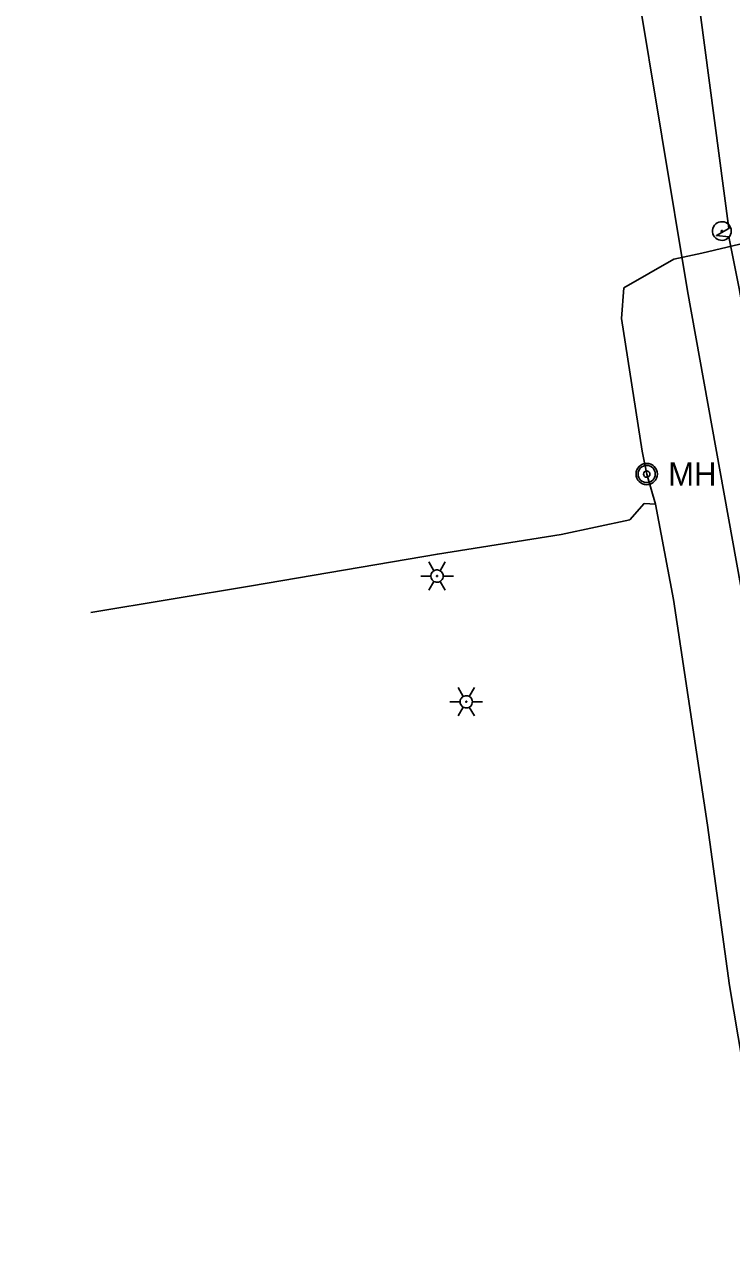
# Model space of a CAD drawing. Extents: x 596028 to 606371, y 330010 to 403088.
# Drawn here: x 604536.2 to 604700.8, y 336030.9 to 336317.8 of the extents above; entities that cross this region are included whole.
import ezdxf

# ---------------------------------------------------------------- set-up
doc = ezdxf.new("R2010")
doc.units = 0
for name, color, linetype in [('Default', 7, 'Continuous'), ('E_LTG', 7, 'Continuous'), ('E_LTG_CID', 7, 'Continuous'), ('E_UTL_E', 7, 'Continuous'), ('E_UTL_E_UG', 7, 'Continuous'), ('E_UTL_FO_UG_QWEST', 7, 'Continuous')]:
    doc.layers.add(name, color=color, linetype=linetype)

# ---------------------------------------------------------------- blocks, each defined once
blk = doc.blocks.new('MH')
at = {"layer": 'Default'}
for radius in [15.2, 12.2, 4.57]:
    blk.add_circle((0, 0), radius, dxfattribs=at)
blk.add_text('MH', height=32.92, dxfattribs=at).set_placement((30.5, -16.5))

msp = doc.modelspace()

# ---------------------------------------------------------------- linework, layer by layer
at = {"layer": 'E_LTG'}
for points in [[(604700.74, 336269.8), (604700.7, 336270.21), (604700.58, 336270.61), (604700.39, 336270.97), (604700.14, 336271.3), (604699.83, 336271.57), (604699.47, 336271.78), (604699.08, 336271.91), (604698.67, 336271.97), (604698.25, 336271.95), (604697.85, 336271.85), (604697.48, 336271.68), (604697.14, 336271.44), (604696.85, 336271.14), (604696.63, 336270.79), (604696.48, 336270.41), (604696.4, 336270), (604696.4, 336269.59), (604696.48, 336269.18), (604696.63, 336268.8), (604696.85, 336268.45), (604697.14, 336268.15), (604697.48, 336267.91), (604697.85, 336267.74), (604698.25, 336267.64), (604698.67, 336267.62), (604699.08, 336267.68), (604699.47, 336267.82), (604699.83, 336268.03), (604700.14, 336268.3), (604700.39, 336268.62), (604700.58, 336268.99), (604700.7, 336269.39), (604700.74, 336269.8)], [(604698.73, 336269.8), (604698.73, 336269.83), (604698.72, 336269.86), (604698.7, 336269.89), (604698.68, 336269.91), (604698.66, 336269.93), (604698.63, 336269.95), (604698.6, 336269.96), (604698.57, 336269.96), (604698.54, 336269.96), (604698.51, 336269.95), (604698.48, 336269.94), (604698.45, 336269.92), (604698.43, 336269.9), (604698.42, 336269.87), (604698.4, 336269.84), (604698.4, 336269.81), (604698.4, 336269.78), (604698.4, 336269.75), (604698.42, 336269.72), (604698.43, 336269.69), (604698.45, 336269.67), (604698.48, 336269.65), (604698.51, 336269.64), (604698.54, 336269.63), (604698.57, 336269.63), (604698.6, 336269.64), (604698.63, 336269.65), (604698.66, 336269.66), (604698.68, 336269.68), (604698.7, 336269.71), (604698.72, 336269.74), (604698.73, 336269.77), (604698.73, 336269.8)], [(604631.51, 336190.72), (604630.32, 336192.78)], [(604632.94, 336190.72), (604634.13, 336192.78)], [(604633.66, 336189.48), (604633.63, 336189.75), (604633.55, 336190.02), (604633.43, 336190.26), (604633.26, 336190.47), (604633.06, 336190.65), (604632.82, 336190.78), (604632.56, 336190.87), (604632.3, 336190.91), (604632.02, 336190.9), (604631.76, 336190.83), (604631.51, 336190.72), (604631.29, 336190.56), (604631.1, 336190.37), (604630.96, 336190.14), (604630.86, 336189.89), (604630.81, 336189.62), (604630.81, 336189.35), (604630.86, 336189.08), (604630.96, 336188.83), (604631.1, 336188.6), (604631.29, 336188.4), (604631.51, 336188.25), (604631.76, 336188.13), (604632.02, 336188.07), (604632.3, 336188.06), (604632.56, 336188.1), (604632.82, 336188.18), (604633.06, 336188.32), (604633.26, 336188.5), (604633.43, 336188.71), (604633.55, 336188.95), (604633.63, 336189.21), (604633.66, 336189.48)], [(604633.66, 336189.48), (604633.63, 336189.75), (604633.55, 336190.02), (604633.43, 336190.26), (604633.26, 336190.47), (604633.06, 336190.65), (604632.82, 336190.78), (604632.56, 336190.87), (604632.3, 336190.91), (604632.02, 336190.9), (604631.76, 336190.83), (604631.51, 336190.72), (604631.29, 336190.56), (604631.1, 336190.37), (604630.96, 336190.14), (604630.86, 336189.89), (604630.81, 336189.62), (604630.81, 336189.35), (604630.86, 336189.08), (604630.96, 336188.83), (604631.1, 336188.6), (604631.29, 336188.4), (604631.51, 336188.25), (604631.76, 336188.13), (604632.02, 336188.07), (604632.3, 336188.06), (604632.56, 336188.1), (604632.82, 336188.18), (604633.06, 336188.32), (604633.26, 336188.5), (604633.43, 336188.71), (604633.55, 336188.95), (604633.63, 336189.21), (604633.66, 336189.48)], [(604633.66, 336189.48), (604633.63, 336189.75), (604633.55, 336190.02), (604633.43, 336190.26), (604633.26, 336190.47), (604633.06, 336190.65), (604632.82, 336190.78), (604632.56, 336190.87), (604632.3, 336190.91), (604632.02, 336190.9), (604631.76, 336190.83), (604631.51, 336190.72), (604631.29, 336190.56), (604631.1, 336190.37), (604630.96, 336190.14), (604630.86, 336189.89), (604630.81, 336189.62), (604630.81, 336189.35), (604630.86, 336189.08), (604630.96, 336188.83), (604631.1, 336188.6), (604631.29, 336188.4), (604631.51, 336188.25), (604631.76, 336188.13), (604632.02, 336188.07), (604632.3, 336188.06), (604632.56, 336188.1), (604632.82, 336188.18), (604633.06, 336188.32), (604633.26, 336188.5), (604633.43, 336188.71), (604633.55, 336188.95), (604633.63, 336189.21), (604633.66, 336189.48)], [(604628.42, 336189.48), (604630.8, 336189.48)], [(604630.32, 336186.18), (604631.51, 336188.25)], [(604632.35, 336189.48), (604632.34, 336189.51), (604632.34, 336189.53), (604632.33, 336189.55), (604632.31, 336189.57), (604632.3, 336189.58), (604632.28, 336189.59), (604632.26, 336189.6), (604632.23, 336189.6), (604632.21, 336189.6), (604632.19, 336189.6), (604632.17, 336189.59), (604632.15, 336189.57), (604632.13, 336189.56), (604632.12, 336189.54), (604632.11, 336189.52), (604632.11, 336189.5), (604632.11, 336189.47), (604632.11, 336189.45), (604632.12, 336189.43), (604632.13, 336189.41), (604632.15, 336189.39), (604632.17, 336189.38), (604632.19, 336189.37), (604632.21, 336189.37), (604632.23, 336189.37), (604632.26, 336189.37), (604632.28, 336189.38), (604632.3, 336189.39), (604632.31, 336189.4), (604632.33, 336189.42), (604632.34, 336189.44), (604632.34, 336189.46), (604632.35, 336189.48)], [(604634.13, 336186.18), (604632.94, 336188.25)], [(604633.66, 336189.48), (604636.04, 336189.48)], [(604638.31, 336161.45), (604637.12, 336163.51)], [(604640.45, 336160.21), (604640.43, 336160.48), (604640.35, 336160.74), (604640.23, 336160.98), (604640.06, 336161.2), (604639.85, 336161.38), (604639.62, 336161.51), (604639.36, 336161.6), (604639.09, 336161.64), (604638.82, 336161.63), (604638.56, 336161.56), (604638.31, 336161.45), (604638.09, 336161.29), (604637.9, 336161.09), (604637.75, 336160.87), (604637.65, 336160.61), (604637.6, 336160.35), (604637.6, 336160.08), (604637.65, 336159.81), (604637.75, 336159.56), (604637.9, 336159.33), (604638.09, 336159.13), (604638.31, 336158.97), (604638.56, 336158.86), (604638.82, 336158.8), (604639.09, 336158.78), (604639.36, 336158.82), (604639.62, 336158.91), (604639.85, 336159.05), (604640.06, 336159.22), (604640.23, 336159.44), (604640.35, 336159.68), (604640.43, 336159.94), (604640.45, 336160.21)], [(604640.45, 336160.21), (604640.43, 336160.48), (604640.35, 336160.74), (604640.23, 336160.98), (604640.06, 336161.2), (604639.85, 336161.38), (604639.62, 336161.51), (604639.36, 336161.6), (604639.09, 336161.64), (604638.82, 336161.63), (604638.56, 336161.56), (604638.31, 336161.45), (604638.09, 336161.29), (604637.9, 336161.09), (604637.75, 336160.87), (604637.65, 336160.61), (604637.6, 336160.35), (604637.6, 336160.08), (604637.65, 336159.81), (604637.75, 336159.56), (604637.9, 336159.33), (604638.09, 336159.13), (604638.31, 336158.97), (604638.56, 336158.86), (604638.82, 336158.8), (604639.09, 336158.78), (604639.36, 336158.82), (604639.62, 336158.91), (604639.85, 336159.05), (604640.06, 336159.22), (604640.23, 336159.44), (604640.35, 336159.68), (604640.43, 336159.94), (604640.45, 336160.21)], [(604640.45, 336160.21), (604640.43, 336160.48), (604640.35, 336160.74), (604640.23, 336160.98), (604640.06, 336161.2), (604639.85, 336161.38), (604639.62, 336161.51), (604639.36, 336161.6), (604639.09, 336161.64), (604638.82, 336161.63), (604638.56, 336161.56), (604638.31, 336161.45), (604638.09, 336161.29), (604637.9, 336161.09), (604637.75, 336160.87), (604637.65, 336160.61), (604637.6, 336160.35), (604637.6, 336160.08), (604637.65, 336159.81), (604637.75, 336159.56), (604637.9, 336159.33), (604638.09, 336159.13), (604638.31, 336158.97), (604638.56, 336158.86), (604638.82, 336158.8), (604639.09, 336158.78), (604639.36, 336158.82), (604639.62, 336158.91), (604639.85, 336159.05), (604640.06, 336159.22), (604640.23, 336159.44), (604640.35, 336159.68), (604640.43, 336159.94), (604640.45, 336160.21)], [(604639.74, 336161.45), (604640.93, 336163.51)], [(604635.21, 336160.21), (604637.6, 336160.21)], [(604637.12, 336156.91), (604638.31, 336158.97)], [(604639.14, 336160.21), (604639.14, 336160.23), (604639.13, 336160.26), (604639.12, 336160.28), (604639.11, 336160.29), (604639.09, 336160.31), (604639.07, 336160.32), (604639.05, 336160.33), (604639.03, 336160.33), (604639.01, 336160.33), (604638.99, 336160.32), (604638.96, 336160.31), (604638.95, 336160.3), (604638.93, 336160.28), (604638.92, 336160.27), (604638.91, 336160.24), (604638.91, 336160.22), (604638.91, 336160.2), (604638.91, 336160.18), (604638.92, 336160.16), (604638.93, 336160.14), (604638.95, 336160.12), (604638.96, 336160.11), (604638.99, 336160.1), (604639.01, 336160.09), (604639.03, 336160.09), (604639.05, 336160.1), (604639.07, 336160.1), (604639.09, 336160.11), (604639.11, 336160.13), (604639.12, 336160.15), (604639.13, 336160.17), (604639.14, 336160.19), (604639.14, 336160.21)], [(604640.93, 336156.91), (604639.74, 336158.97)], [(604640.45, 336160.21), (604642.83, 336160.21)]]:
    msp.add_lwpolyline(points, dxfattribs=at)
at = {"layer": 'E_LTG_CID'}
msp.add_lwpolyline([(604774.25, 335835.23), (604767.31, 335879.89), (604757.37, 335915.43), (604754.96, 335952.57), (604741.97, 336023.81), (604738.31, 336039.42), (604736.98, 336059.55), (604725.78, 336098.43), (604729.26, 336099.72), (604729.07, 336107.31), (604715.78, 336182.17), (604702.58, 336256.41), (604700.19, 336268.42), (604697.28, 336268.75), (604700.18, 336270.36), (604692.32, 336329.51), (604678.95, 336405.71), (604671.73, 336440.44), (604669.09, 336440.78), (604671.37, 336442.9), (604666.86, 336479.67), (604654.36, 336555.45), (604643.97, 336613.3)], dxfattribs=at)
at = {"layer": 'E_UTL_E_UG'}
for points in [[(604724.7, 335948.32), (604716.67, 335995.96), (604708.45, 336045.93), (604700.33, 336094.17), (604695.23, 336131.52), (604687.32, 336184.01), (604683.1, 336206.24), (604681.05, 336213.23), (604679.96, 336218.59), (604675.17, 336249.43), (604675.71, 336256.56), (604687.33, 336263.29), (604693.86, 336264.66), (604704.02, 336267.04)], [(604551.63, 336181.03), (604588.99, 336187.23), (604632.33, 336194.6), (604661.1, 336199.18), (604677.09, 336202.55), (604680.44, 336206.34), (604683.1, 336206.24)]]:
    msp.add_lwpolyline(points, dxfattribs=at)
at = {"layer": 'E_UTL_FO_UG_QWEST'}
msp.add_lwpolyline([(604764.64, 335825.63), (604754.97, 335878.92), (604751.95, 335896.96), (604749.11, 335915.96), (604739.53, 335966.31), (604727.68, 336038.53), (604715.74, 336106.65), (604703.91, 336181.91), (604690.54, 336255.88), (604678.58, 336327.99), (604664.78, 336404.76), (604651.78, 336480.07), (604639.96, 336554.44), (604628.34, 336626.54), (604615.77, 336699.8), (604611.3, 336722.29), (604607.39, 336749.34), (604597.4, 336819.21), (604583.07, 336892.17), (604574.68, 336963.66), (604563.59, 337039.69), (604549.05, 337114), (604536.54, 337190.93), (604536.2, 337193.87)], dxfattribs=at)

# ---------------------------------------------------------------- block references
at = {"layer": 'E_UTL_E', "xscale": 0.16404166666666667, "yscale": 0.16404166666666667}
msp.add_blockref('MH', (604681.05, 336213.23), dxfattribs=at)

doc.saveas('drawing.dxf')
